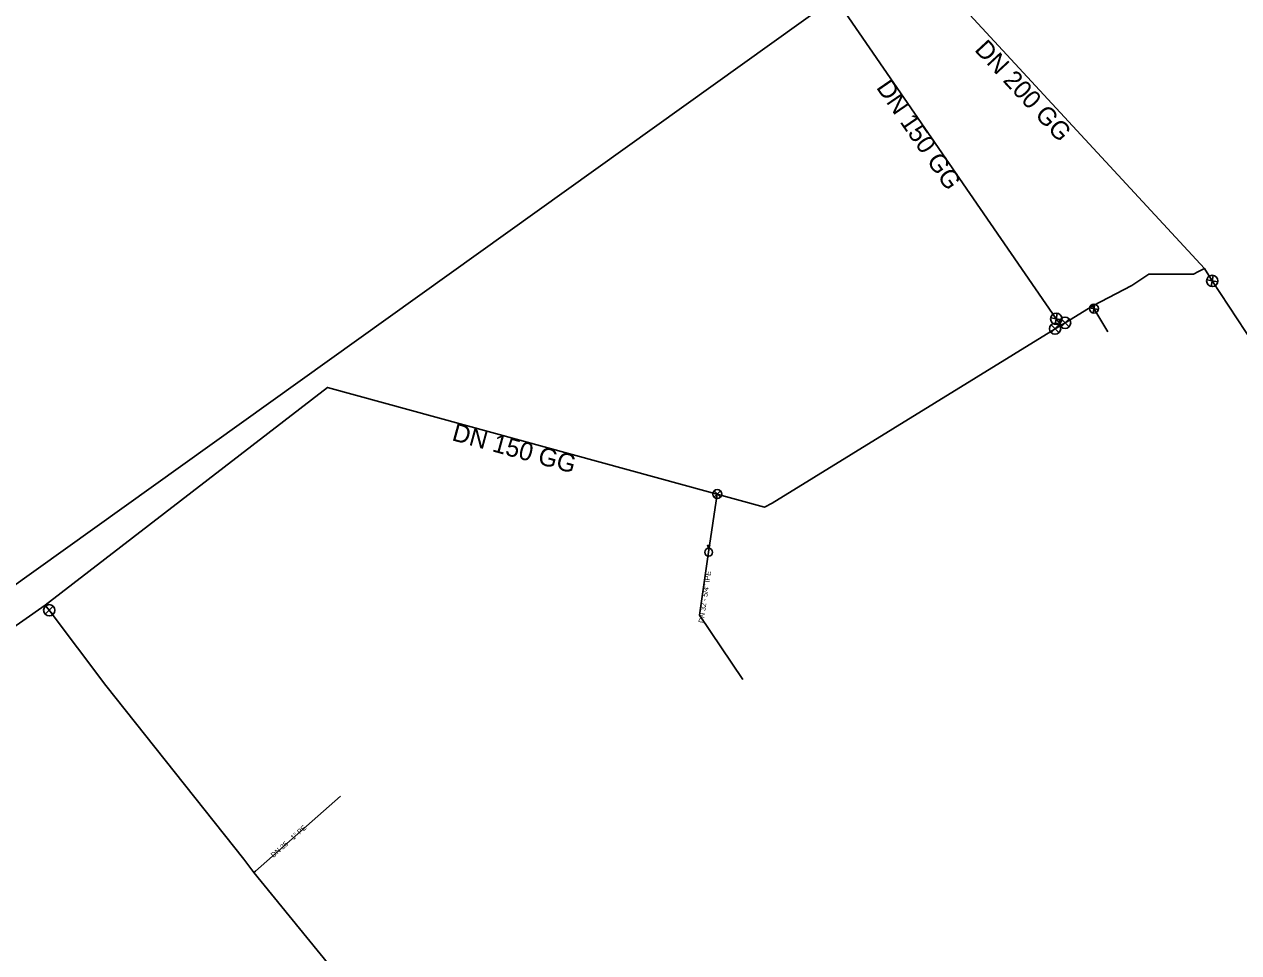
# Model space of a CAD drawing. Extents: x -4927528 to -4924018, y -11264917 to -11262544.
# Drawn here: x -4926456 to -4925380, y -11264100 to -11263278 of the extents above; entities that cross this region are included whole.
import ezdxf

# ---------------------------------------------------------------- set-up
doc = ezdxf.new("R2010")
doc.units = 0
for name, color, linetype in [('_pripojka_prevzato_z_dokumentace_', 7, 'Continuous'), ('_pripojka_priblizne_', 7, 'Continuous'), ('_voda_smvak_prevzato_z_dokumentace_', 7, 'Continuous'), ('Default', 7, 'Continuous'), ('MoLevel 27', 7, 'Continuous'), ('MoLevel 30', 7, 'Continuous'), ('MoLevel 32', 7, 'Continuous'), ('MoLevel 46', 7, 'Continuous'), ('MoLevel 53', 7, 'Continuous'), ('MoLevel 55', 7, 'Continuous')]:
    doc.layers.add(name, color=color, linetype=linetype)

# ---------------------------------------------------------------- blocks, each defined once
blk = doc.blocks.new('_uzaver_')
at = {"layer": 'Default'}
for p, q in [((-0.00035, -0.00035), (0.00035, 0.00035)), ((0.00035, -0.00035), (-0.00035, 0.00035))]:
    blk.add_line(p, q, dxfattribs=at)
for radius in [0.0005, 0.000025]:
    blk.add_circle((0, 0), radius, dxfattribs=at)
blk = doc.blocks.new('_uzaver_pripojka_')
at = {"layer": 'Default'}
for p, q in [((-0.00035, -0.00035), (0.00035, 0.00035)), ((0.00035, -0.00035), (-0.00035, 0.00035))]:
    blk.add_line(p, q, dxfattribs=at)
for radius in [0.0005, 0.000025]:
    blk.add_circle((0, 0), radius, dxfattribs=at)
blk = doc.blocks.new('_sachta_voda_')
at = {"layer": 'Default'}
blk.add_lwpolyline([(-0.0001, 0.00065), (0, 0.00035), (0.0001, 0.00065)], dxfattribs=at)
blk.add_circle((0, 0), 0.00035, dxfattribs=at)

msp = doc.modelspace()

# ---------------------------------------------------------------- linework, layer by layer
at = {"layer": '_pripojka_prevzato_z_dokumentace_'}
for points in [[(-4925496.4, -11263550.3), (-4925508.7, -11263529.8), (-4925509.6, -11263527.3)], [(-4926252.4, -11264029.2), (-4926250.9, -11264028.1), (-4926175.8, -11263961.5)]]:
    msp.add_lwpolyline(points, dxfattribs=at)
at = {"layer": '_pripojka_priblizne_'}
msp.add_line((-4925842.2, -11263694.1), (-4925849.8, -11263745.6), dxfattribs=at)
msp.add_lwpolyline([(-4925849.8, -11263745.6), (-4925858, -11263801.4), (-4925819.5, -11263858.2)], dxfattribs=at)
at = {"layer": '_voda_smvak_prevzato_z_dokumentace_'}
for p, q in [((-4925410.7, -11263494.2), (-4925671.7, -11263212.2)), ((-4925734.8, -11263258.9), (-4925542, -11263538.9)), ((-4925416, -11263497), (-4925410.7, -11263494.2)), ((-4925410.7, -11263494.2), (-4925403.9, -11263505.3)), ((-4925537.7, -11263544.6), (-4925543.1, -11263547.6)), ((-4925542, -11263538.9), (-4925537.7, -11263544.6)), ((-4925537.7, -11263544.6), (-4925534.2, -11263542.4)), ((-4926433.6, -11263797), (-4926437.3, -11263792.5))]:
    msp.add_line(p, q, dxfattribs=at)
for points in [[(-4925741.8, -11263257.7), (-4926471.3, -11263779.7), (-4926626.3, -11263906.7), (-4926783.8, -11264042.7), (-4926826.3, -11264075.2), (-4926870.7, -11264137), (-4927005.3, -11264324.4), (-4927247.9, -11264639.2), (-4927375.4, -11264800)], [(-4925534.2, -11263542.4), (-4925509.6, -11263527.3), (-4925475.1, -11263509.3), (-4925460.1, -11263499.4), (-4925420.6, -11263499.4), (-4925416, -11263497)], [(-4925403.9, -11263505.3), (-4925352.4, -11263583.7), (-4925288.4, -11263685), (-4925260, -11263727.6), (-4925251.4, -11263744), (-4925208.5, -11263811.6), (-4925176.7, -11263856.6), (-4925129.1, -11263933.4), (-4925041.8, -11264068.8), (-4925022.2, -11264093.4)], [(-4925543.1, -11263547.6), (-4925793.6, -11263702.1), (-4925800.2, -11263705.6), (-4926187.2, -11263599.7), (-4926437.3, -11263792.5)], [(-4926437.3, -11263792.5), (-4926527.5, -11263855.5), (-4926618.2, -11263919.4), (-4926768.5, -11264062.5), (-4926828.7, -11264133.9), (-4926875.7, -11264199.1), (-4927006, -11264381.9), (-4927278.6, -11264765.7), (-4927326.9, -11264843.6)], [(-4925759, -11264662.1), (-4925786.7, -11264632.1), (-4925887.7, -11264500.4), (-4925963.1, -11264402.1), (-4925994.9, -11264365.7), (-4926009.6, -11264339.3), (-4926068.7, -11264267.1), (-4926142.6, -11264168.2), (-4926187.3, -11264109.2), (-4926252.4, -11264029.2), (-4926261.4, -11264017.3), (-4926383.4, -11263863.6), (-4926433.6, -11263797)]]:
    msp.add_lwpolyline(points, dxfattribs=at)

# ---------------------------------------------------------------- block references
at = {"layer": 'MoLevel 27', "yscale": 10000.000000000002}
for p, xscale, rotation in [((-4925403.9, -11263505.3), 10000, -55.13091111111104), ((-4925542, -11263538.9), 9999.999999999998, -55.52404444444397)]:
    msp.add_blockref('_uzaver_', p, dxfattribs=dict(at, xscale=xscale, rotation=rotation))
at = {"layer": 'MoLevel 27', "xscale": 10000, "yscale": 10000}
for p in [(-4925534.2, -11263542.4), (-4925543.1, -11263547.6), (-4926433.6, -11263797)]:
    msp.add_blockref('_uzaver_', p, dxfattribs=at)
at = {"layer": 'MoLevel 30', "xscale": 10000, "yscale": 10000}
msp.add_blockref('_sachta_voda_', (-4925849.8, -11263745.6), dxfattribs=at)
at = {"layer": 'MoLevel 53', "xscale": 7999.999999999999, "yscale": 8000.000000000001, "rotation": -145.10590000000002}
msp.add_blockref('_uzaver_pripojka_', (-4925508.7, -11263529.8), dxfattribs=at)
at = {"layer": 'MoLevel 53', "xscale": 7999.999999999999, "yscale": 7999.999999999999}
msp.add_blockref('_uzaver_pripojka_', (-4925842.2, -11263694.1), dxfattribs=at)

# ---------------------------------------------------------------- texts
at = {"layer": 'MoLevel 32'}
msp.add_text("DN 32 - 5/4'' IPE", height=4.55, rotation=81.6282, dxfattribs=at).set_placement((-4925854.4, -11263808.5))
at = {"layer": 'MoLevel 46'}
for s, rotation, p in [('DN 200 GG', 312.7874, (-4925615.1, -11263301)), ('DN 150 GG', 304.5513, (-4925701.9, -11263334)), ('DN 150 GG', 344.6998, (-4926077.9, -11263646.3))]:
    msp.add_text(s, height=16.05, rotation=rotation, dxfattribs=at).set_placement(p)
at = {"layer": 'MoLevel 55'}
msp.add_text("DN 25 - 1'' PE", height=4.55, rotation=41.5468, dxfattribs=at).set_placement((-4926235, -11264016.3))

doc.saveas('drawing.dxf')
